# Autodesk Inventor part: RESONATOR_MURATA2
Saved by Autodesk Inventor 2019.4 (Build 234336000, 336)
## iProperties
Created: 2021-02
Part Number: RESONATOR_MURATA2
Material: Generic
Document SubType Name: Modeling
Designer: Administrator
Density: 1 g/cm^3
Appearance: Default
Title: RESONATOR_MURATA2
Author: Administrator
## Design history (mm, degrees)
feature "Body1"
body "Solid1"
